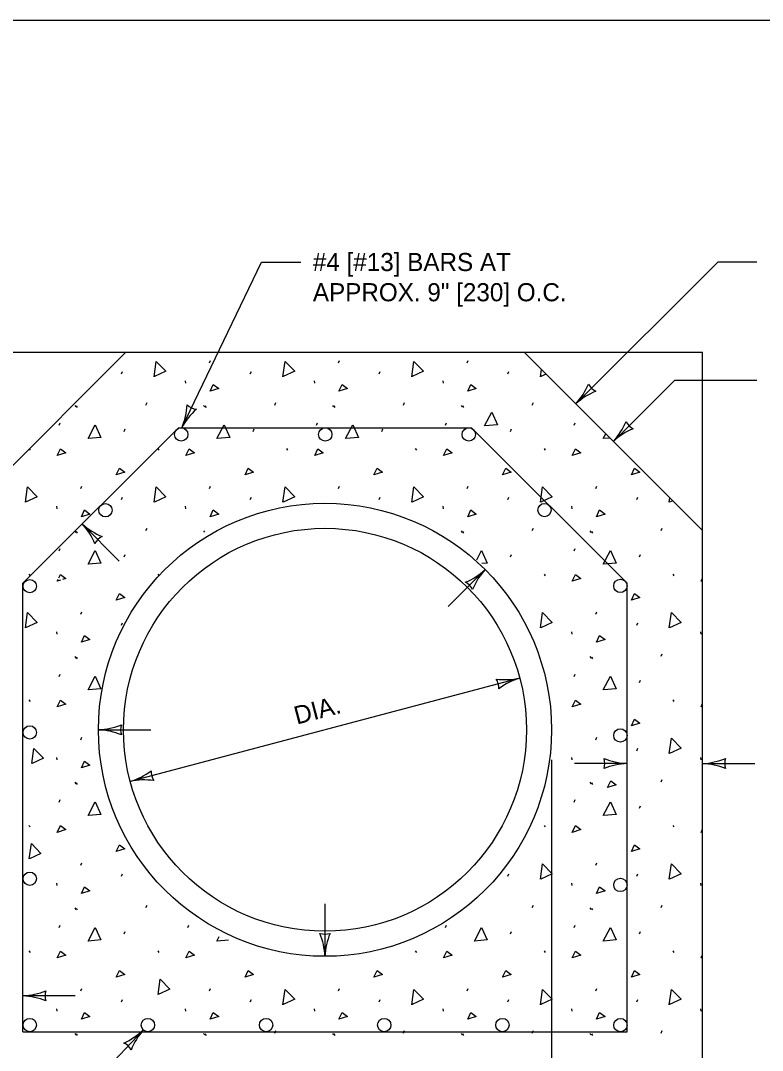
# Model space of a CAD drawing. Extents: x 49991.4 to 50021, y 49987.6 to 50011.4.
# Drawn here: x 50001.927 to 50004.383, y 50007.853 to 50011.263 of the extents above; entities that cross this region are included whole.
import ezdxf

# ---------------------------------------------------------------- set-up
doc = ezdxf.new("R2010")
doc.units = 0
for name, color, linetype in [('Level 1', 7, 'Continuous'), ('Level 2', 7, 'Continuous'), ('Level 3', 7, 'Continuous'), ('Level 4', 7, 'Continuous')]:
    doc.layers.add(name, color=color, linetype=linetype)

msp = doc.modelspace()

# ---------------------------------------------------------------- linework, layer by layer
at = {"layer": 'Level 1'}
for p, q in [((50001.6843, 50009.5741), (50002.275, 50010.1648)), ((50002.275, 50010.1648), (50003.594, 50010.1648)), ((50004.1843, 50009.5745), (50003.594, 50010.1648)), ((50002.5522, 50010.1293), (50002.5557, 50010.1373)), ((50002.9785, 50010.1293), (50002.9821, 50010.1373)), ((50003.4049, 50010.1293), (50003.4085, 50010.1373)), ((50002.2608, 50010.0929), (50002.2643, 50010.1009)), ((50002.6871, 50010.0929), (50002.6907, 50010.1009)), ((50003.1135, 50010.0929), (50003.1171, 50010.1009)), ((50003.5399, 50010.0929), (50003.5434, 50010.1009)), ((50002.4719, 50010.0706), (50002.4728, 50010.0626)), ((50002.8983, 50010.0706), (50002.8992, 50010.0626)), ((50003.3246, 50010.0706), (50003.3255, 50010.0626)), ((50002.1061, 50009.9889), (50002.1097, 50009.9836)), ((50002.1107, 50009.9869), (50002.1142, 50009.9816)), ((50002.3416, 50009.9899), (50002.3451, 50009.9979)), ((50002.5325, 50009.9889), (50002.536, 50009.9836)), ((50002.537, 50009.9869), (50002.5406, 50009.9816)), ((50002.7679, 50009.9899), (50002.7715, 50009.9979)), ((50002.9589, 50009.9889), (50002.9624, 50009.9836)), ((50002.9634, 50009.9869), (50002.967, 50009.9816)), ((50003.1943, 50009.9899), (50003.1979, 50009.9979)), ((50003.3852, 50009.9889), (50003.3888, 50009.9836)), ((50003.3898, 50009.9869), (50003.3934, 50009.9816)), ((50003.6207, 50009.9899), (50003.6242, 50009.9979)), ((50001.9343, 50009.3998), (50002.4493, 50009.9148)), ((50002.0537, 50009.9231), (50002.0573, 50009.9311)), ((50002.2696, 50009.9027), (50002.2732, 50009.9107)), ((50002.4493, 50009.9148), (50003.4196, 50009.9148)), ((50002.696, 50009.9027), (50002.6996, 50009.9107)), ((50002.9065, 50009.9231), (50002.91, 50009.9311)), ((50003.1224, 50009.9027), (50003.1259, 50009.9107)), ((50003.3328, 50009.9231), (50003.3364, 50009.9311)), ((50003.4196, 50009.9148), (50003.9343, 50009.4004)), ((50003.5488, 50009.9027), (50003.5523, 50009.9107)), ((50003.7592, 50009.9231), (50003.7628, 50009.9311)), ((50001.955, 50009.8448), (50001.9578, 50009.8405)), ((50002.3806, 50009.8458), (50002.3842, 50009.8405)), ((50002.807, 50009.8458), (50002.8106, 50009.8405)), ((50003.2334, 50009.8458), (50003.2369, 50009.8405)), ((50003.6598, 50009.8458), (50003.6633, 50009.8405)), ((50002.1258, 50009.7135), (50002.1293, 50009.7215)), ((50002.5522, 50009.7135), (50002.5557, 50009.7215)), ((50002.9785, 50009.7135), (50002.9821, 50009.7215)), ((50003.4049, 50009.7135), (50003.4085, 50009.7215)), ((50003.8313, 50009.7135), (50003.8348, 50009.7215)), ((50002.2608, 50009.6771), (50002.2643, 50009.6851)), ((50002.6871, 50009.6771), (50002.6907, 50009.6851)), ((50003.1135, 50009.6771), (50003.1171, 50009.6851)), ((50003.5399, 50009.6771), (50003.5434, 50009.6851)), ((50003.9663, 50009.6771), (50003.9698, 50009.6851)), ((50002.0455, 50009.6548), (50002.0464, 50009.6468)), ((50002.4719, 50009.6548), (50002.4728, 50009.6468)), ((50003.3246, 50009.6548), (50003.3255, 50009.6468)), ((50003.751, 50009.6548), (50003.7519, 50009.6468)), ((50002.1061, 50009.5731), (50002.1097, 50009.5678)), ((50002.1107, 50009.5711), (50002.1142, 50009.5657)), ((50002.3416, 50009.5741), (50002.3451, 50009.5821)), ((50002.5325, 50009.5731), (50002.5349, 50009.5695)), ((50003.3852, 50009.5731), (50003.3888, 50009.5678)), ((50003.3898, 50009.5711), (50003.3934, 50009.5657)), ((50003.6207, 50009.5741), (50003.6242, 50009.5821)), ((50003.8116, 50009.5731), (50003.8152, 50009.5678)), ((50003.8162, 50009.5711), (50003.8197, 50009.5657)), ((50004.0471, 50009.5741), (50004.0506, 50009.5821)), ((50004.1843, 50007.6648), (50004.1843, 50009.5745)), ((50002.0537, 50009.5073), (50002.0573, 50009.5153)), ((50003.7592, 50009.5073), (50003.7628, 50009.5153)), ((50002.2696, 50009.4869), (50002.2732, 50009.4948)), ((50003.5488, 50009.4869), (50003.5523, 50009.4948)), ((50003.9751, 50009.4869), (50003.9787, 50009.4948)), ((50001.9543, 50009.43), (50001.9578, 50009.4247)), ((50002.3806, 50009.43), (50002.3842, 50009.4247)), ((50003.6598, 50009.43), (50003.6633, 50009.4247)), ((50004.0861, 50009.43), (50004.0897, 50009.4247)), ((50001.9343, 50007.9148), (50001.9343, 50009.3998)), ((50003.9343, 50007.9148), (50003.9343, 50009.4004)), ((50002.1258, 50009.2977), (50002.1293, 50009.3057)), ((50003.8313, 50009.2977), (50003.8348, 50009.3057)), ((50002.2608, 50009.2613), (50002.2643, 50009.2693)), ((50003.9663, 50009.2613), (50003.9698, 50009.2693)), ((50002.0455, 50009.239), (50002.0464, 50009.231)), ((50003.751, 50009.239), (50003.7519, 50009.231)), ((50004.1774, 50009.239), (50004.1783, 50009.231)), ((50002.1061, 50009.1573), (50002.1097, 50009.152)), ((50002.1107, 50009.1553), (50002.1142, 50009.1499)), ((50003.8116, 50009.1573), (50003.8152, 50009.152)), ((50003.8162, 50009.1553), (50003.8197, 50009.1499)), ((50004.0471, 50009.1583), (50004.0506, 50009.1663)), ((50002.0537, 50009.0915), (50002.0573, 50009.0995)), ((50003.7592, 50009.0915), (50003.7628, 50009.0995)), ((50003.9751, 50009.071), (50003.9787, 50009.079)), ((50001.9543, 50009.0142), (50001.9578, 50009.0089)), ((50004.0861, 50009.0142), (50004.0897, 50009.0089)), ((50002.1258, 50008.8819), (50002.1293, 50008.8899)), ((50003.8313, 50008.8819), (50003.8348, 50008.8899)), ((50003.9663, 50008.8455), (50003.9698, 50008.8535)), ((50002.0455, 50008.8232), (50002.0464, 50008.8152)), ((50003.751, 50008.8232), (50003.7519, 50008.8152)), ((50004.1774, 50008.8232), (50004.1783, 50008.8152)), ((50004.0471, 50008.7425), (50004.0506, 50008.7505)), ((50002.1061, 50008.7415), (50002.1097, 50008.7361)), ((50002.1107, 50008.7394), (50002.1142, 50008.7341)), ((50003.8116, 50008.7415), (50003.8152, 50008.7361)), ((50003.8162, 50008.7394), (50003.8197, 50008.7341)), ((50002.0537, 50008.6756), (50002.0573, 50008.6836)), ((50003.7592, 50008.6756), (50003.7628, 50008.6836)), ((50003.9751, 50008.6552), (50003.9787, 50008.6632)), ((50001.9543, 50008.5984), (50001.9578, 50008.5931)), ((50003.6598, 50008.5984), (50003.6633, 50008.5931)), ((50004.0861, 50008.5984), (50004.0897, 50008.5931)), ((50002.1258, 50008.4661), (50002.1293, 50008.4741)), ((50003.8313, 50008.4661), (50003.8348, 50008.4741)), ((50002.0455, 50008.4074), (50002.0464, 50008.3994)), ((50002.2608, 50008.4297), (50002.2643, 50008.4377)), ((50003.5399, 50008.4297), (50003.5434, 50008.4377)), ((50003.751, 50008.4074), (50003.7519, 50008.3994)), ((50003.9663, 50008.4297), (50003.9698, 50008.4377)), ((50004.1774, 50008.4074), (50004.1783, 50008.3994)), ((50002.1061, 50008.3257), (50002.1097, 50008.3203)), ((50002.1107, 50008.3236), (50002.1142, 50008.3183)), ((50002.3416, 50008.3267), (50002.3451, 50008.3346)), ((50003.6207, 50008.3267), (50003.6242, 50008.3346)), ((50003.8116, 50008.3257), (50003.8152, 50008.3203)), ((50003.8162, 50008.3236), (50003.8197, 50008.3183)), ((50004.0471, 50008.3267), (50004.0506, 50008.3346)), ((50002.0537, 50008.2598), (50002.0573, 50008.2678)), ((50002.4801, 50008.2598), (50002.4836, 50008.2678)), ((50003.3328, 50008.2598), (50003.3364, 50008.2678)), ((50003.7592, 50008.2598), (50003.7628, 50008.2678)), ((50002.2696, 50008.2394), (50002.2732, 50008.2474)), ((50003.5488, 50008.2394), (50003.5523, 50008.2474)), ((50003.9751, 50008.2394), (50003.9787, 50008.2474)), ((50001.9543, 50008.1826), (50001.9578, 50008.1772)), ((50002.3806, 50008.1826), (50002.3842, 50008.1772)), ((50003.2334, 50008.1826), (50003.2369, 50008.1772)), ((50003.6598, 50008.1826), (50003.6633, 50008.1772)), ((50004.0861, 50008.1826), (50004.0897, 50008.1772)), ((50002.1258, 50008.0503), (50002.1293, 50008.0583)), ((50002.5522, 50008.0503), (50002.5557, 50008.0583)), ((50002.9785, 50008.0503), (50002.9821, 50008.0583)), ((50003.4049, 50008.0503), (50003.4085, 50008.0583)), ((50003.8313, 50008.0503), (50003.8348, 50008.0583)), ((50002.2608, 50008.0138), (50002.2643, 50008.0218)), ((50002.6871, 50008.0138), (50002.6907, 50008.0218)), ((50003.1135, 50008.0138), (50003.1171, 50008.0218)), ((50003.5399, 50008.0138), (50003.5434, 50008.0218)), ((50003.9663, 50008.0138), (50003.9698, 50008.0218)), ((50002.0455, 50007.9915), (50002.0464, 50007.9836)), ((50002.4719, 50007.9915), (50002.4728, 50007.9836)), ((50002.8983, 50007.9915), (50002.8992, 50007.9836)), ((50003.3246, 50007.9915), (50003.3255, 50007.9836)), ((50003.751, 50007.9915), (50003.7519, 50007.9836)), ((50004.1774, 50007.9915), (50004.1783, 50007.9836)), ((50001.9343, 50007.9148), (50003.9343, 50007.9148)), ((50002.1061, 50007.9098), (50002.1097, 50007.9045)), ((50002.1107, 50007.9078), (50002.1142, 50007.9025)), ((50002.5325, 50007.9098), (50002.536, 50007.9045)), ((50002.537, 50007.9078), (50002.5406, 50007.9025)), ((50002.7679, 50007.9108), (50002.7715, 50007.9188)), ((50002.9589, 50007.9098), (50002.9624, 50007.9045)), ((50002.9634, 50007.9078), (50002.967, 50007.9025)), ((50003.1943, 50007.9108), (50003.1979, 50007.9188)), ((50003.3852, 50007.9098), (50003.3888, 50007.9045)), ((50003.3898, 50007.9078), (50003.3934, 50007.9025)), ((50003.6207, 50007.9108), (50003.6242, 50007.9188)), ((50003.8116, 50007.9098), (50003.8152, 50007.9045)), ((50003.8162, 50007.9078), (50003.8197, 50007.9025)), ((50004.0471, 50007.9108), (50004.0506, 50007.9188))]:
    msp.add_line(p, q, dxfattribs=at)
msp.add_lwpolyline([(50008.6146, 50011.2628), (50000.3356, 50011.2628), (50000.3356, 50000.0624), (50008.6146, 50000.0624)], close=True, dxfattribs=at)
for points in [[(50002.3688, 50010.0837), (50002.3758, 50010.1345), (50002.4076, 50010.1017), (50002.3696, 50010.084)], [(50002.7952, 50010.0837), (50002.8022, 50010.1345), (50002.834, 50010.1017), (50002.796, 50010.084)], [(50003.2215, 50010.0837), (50003.2286, 50010.1345), (50003.2604, 50010.1017), (50003.2224, 50010.084)], [(50003.6479, 50010.0837), (50003.6512, 50010.1072)], [(50003.6662, 50010.0921), (50003.6488, 50010.084)], [(50002.1555, 50010.0453), (50002.156, 50010.045), (50002.1548, 50010.0446)], [(50002.5539, 50010.0361), (50002.5646, 50010.0583), (50002.5823, 50010.045), (50002.5539, 50010.0361)], [(50002.9803, 50010.0361), (50002.991, 50010.0583), (50003.0087, 50010.045), (50002.9803, 50010.0361)], [(50003.4067, 50010.0361), (50003.4173, 50010.0583), (50003.4351, 50010.045), (50003.4067, 50010.0361)], [(50003.4626, 50009.9207), (50003.4866, 50009.966), (50003.5052, 50009.9242), (50003.4635, 50009.9207)], [(50002.1498, 50009.8787), (50002.1737, 50009.924), (50002.1924, 50009.8822), (50002.1506, 50009.8787)], [(50002.5761, 50009.8787), (50002.6001, 50009.924), (50002.6188, 50009.8822), (50002.577, 50009.8787)], [(50003.0025, 50009.8787), (50003.0265, 50009.924), (50003.0451, 50009.8822), (50003.0034, 50009.8787)], [(50003.8553, 50009.8787), (50003.8638, 50009.8948)], [(50003.878, 50009.8805), (50003.8561, 50009.8787)], [(50002.0475, 50009.8227), (50002.0582, 50009.8449), (50002.0759, 50009.8316), (50002.0475, 50009.8227)], [(50002.4739, 50009.8227), (50002.4845, 50009.8449), (50002.5023, 50009.8316), (50002.4739, 50009.8227)], [(50002.9003, 50009.8227), (50002.9109, 50009.8449), (50002.9287, 50009.8316), (50002.9003, 50009.8227)], [(50003.3266, 50009.8227), (50003.3373, 50009.8449), (50003.355, 50009.8316), (50003.3266, 50009.8227)], [(50003.753, 50009.8227), (50003.7637, 50009.8449), (50003.7814, 50009.8316), (50003.753, 50009.8227)], [(50002.2432, 50009.7593), (50002.2538, 50009.7815), (50002.2716, 50009.7681), (50002.2432, 50009.7593)], [(50002.6695, 50009.7593), (50002.6802, 50009.7815), (50002.698, 50009.7681), (50002.6695, 50009.7593)], [(50003.0959, 50009.7593), (50003.1066, 50009.7815), (50003.1243, 50009.7681), (50003.0959, 50009.7593)], [(50003.5223, 50009.7593), (50003.533, 50009.7815), (50003.5507, 50009.7681), (50003.5223, 50009.7593)], [(50003.9487, 50009.7593), (50003.9593, 50009.7815), (50003.9771, 50009.7681), (50003.9487, 50009.7593)], [(50001.9424, 50009.6679), (50001.9495, 50009.7187), (50001.9813, 50009.6858), (50001.9432, 50009.6682)], [(50002.3688, 50009.6679), (50002.3758, 50009.7187), (50002.4076, 50009.6858), (50002.3696, 50009.6682)], [(50002.7952, 50009.6679), (50002.8022, 50009.7187), (50002.834, 50009.6858), (50002.796, 50009.6682)], [(50003.2215, 50009.6679), (50003.2286, 50009.7187), (50003.2604, 50009.6858), (50003.2224, 50009.6682)], [(50003.6479, 50009.6679), (50003.655, 50009.7187), (50003.6868, 50009.6858), (50003.6488, 50009.6682)], [(50004.0743, 50009.6679), (50004.0763, 50009.6824)], [(50004.0856, 50009.6731), (50004.0751, 50009.6682)], [(50002.1276, 50009.6203), (50002.1382, 50009.6425), (50002.156, 50009.6292), (50002.1276, 50009.6203)], [(50002.5539, 50009.6203), (50002.5646, 50009.6425), (50002.5823, 50009.6292), (50002.5539, 50009.6203)], [(50003.4067, 50009.6203), (50003.4173, 50009.6425), (50003.4351, 50009.6292), (50003.4067, 50009.6203)], [(50003.8331, 50009.6203), (50003.8437, 50009.6425), (50003.8615, 50009.6292), (50003.8331, 50009.6203)], [(50002.1498, 50009.4629), (50002.1737, 50009.5082), (50002.1924, 50009.4664), (50002.1506, 50009.4629)], [(50003.4368, 50009.4778), (50003.4529, 50009.5082), (50003.4715, 50009.4664), (50003.4539, 50009.4649)], [(50003.8553, 50009.4629), (50003.8792, 50009.5082), (50003.8979, 50009.4664), (50003.8561, 50009.4629)], [(50002.0527, 50009.4178), (50002.0582, 50009.4291), (50002.0759, 50009.4158), (50002.0653, 50009.4125)], [(50003.753, 50009.4069), (50003.7637, 50009.4291), (50003.7814, 50009.4158), (50003.753, 50009.4069)], [(50002.0475, 50009.4069), (50002.0507, 50009.4136)], [(50002.0583, 50009.4103), (50002.0475, 50009.4069)], [(50004.1794, 50009.4069), (50004.1843, 50009.4172)], [(50004.1843, 50009.4084), (50004.1794, 50009.4069)], [(50002.2432, 50009.3435), (50002.2538, 50009.3657), (50002.2716, 50009.3523), (50002.2432, 50009.3435)], [(50003.9487, 50009.3435), (50003.9593, 50009.3657), (50003.9771, 50009.3523), (50003.9487, 50009.3435)], [(50001.9424, 50009.2521), (50001.9495, 50009.3029), (50001.9813, 50009.27), (50001.9432, 50009.2524)], [(50003.6479, 50009.2521), (50003.655, 50009.3029), (50003.6868, 50009.27), (50003.6488, 50009.2524)], [(50004.0743, 50009.2521), (50004.0813, 50009.3029), (50004.1131, 50009.27), (50004.0751, 50009.2524)], [(50002.1276, 50009.2045), (50002.1382, 50009.2267), (50002.156, 50009.2133), (50002.1276, 50009.2045)], [(50003.8331, 50009.2045), (50003.8437, 50009.2267), (50003.8615, 50009.2133), (50003.8331, 50009.2045)], [(50002.1498, 50009.0471), (50002.1737, 50009.0923), (50002.1924, 50009.0506), (50002.1506, 50009.0471)], [(50003.8553, 50009.0471), (50003.8792, 50009.0923), (50003.8979, 50009.0506), (50003.8561, 50009.0471)], [(50002.0475, 50008.9911), (50002.0582, 50009.0133), (50002.0759, 50009), (50002.0475, 50008.9911)], [(50003.753, 50008.9911), (50003.7637, 50009.0133), (50003.7814, 50009), (50003.753, 50008.9911)], [(50004.1794, 50008.9911), (50004.1843, 50009.0014)], [(50004.1843, 50008.9926), (50004.1794, 50008.9911)], [(50003.9487, 50008.9276), (50003.9593, 50008.9498), (50003.9771, 50008.9365), (50003.9487, 50008.9276)], [(50004.0743, 50008.8363), (50004.0813, 50008.887), (50004.1131, 50008.8542), (50004.0751, 50008.8366)], [(50001.9635, 50008.8027), (50001.9706, 50008.8534), (50002.0024, 50008.8206), (50001.9643, 50008.803)], [(50002.1276, 50008.7886), (50002.1382, 50008.8108), (50002.156, 50008.7975), (50002.1276, 50008.7886)], [(50003.8696, 50008.7232), (50003.8802, 50008.7454), (50003.898, 50008.7321), (50003.8696, 50008.7232)], [(50002.1498, 50008.6312), (50002.1737, 50008.6765), (50002.1924, 50008.6348), (50002.1506, 50008.6312)], [(50003.8553, 50008.6312), (50003.8792, 50008.6765), (50003.8979, 50008.6348), (50003.8561, 50008.6312)], [(50002.0475, 50008.5753), (50002.0582, 50008.5975), (50002.0759, 50008.5842), (50002.0475, 50008.5753)], [(50003.753, 50008.5753), (50003.7637, 50008.5975), (50003.7814, 50008.5842), (50003.753, 50008.5753)], [(50004.1794, 50008.5753), (50004.1843, 50008.5856)], [(50004.1843, 50008.5768), (50004.1794, 50008.5753)], [(50001.9551, 50008.4878), (50001.9622, 50008.5385), (50001.994, 50008.5057), (50001.9559, 50008.4881)], [(50002.2432, 50008.5118), (50002.2538, 50008.534), (50002.2716, 50008.5207), (50002.2432, 50008.5118)], [(50003.9487, 50008.5118), (50003.9593, 50008.534), (50003.9771, 50008.5207), (50003.9487, 50008.5118)], [(50003.6479, 50008.4205), (50003.655, 50008.4712), (50003.6868, 50008.4384), (50003.6488, 50008.4208)], [(50004.0743, 50008.4205), (50004.0813, 50008.4712), (50004.1131, 50008.4384), (50004.0751, 50008.4208)], [(50002.1276, 50008.3728), (50002.1382, 50008.395), (50002.156, 50008.3817), (50002.1276, 50008.3728)], [(50003.8331, 50008.3728), (50003.8437, 50008.395), (50003.8615, 50008.3817), (50003.8331, 50008.3728)], [(50002.1498, 50008.2154), (50002.1737, 50008.2607), (50002.1924, 50008.219), (50002.1506, 50008.2154)], [(50003.4289, 50008.2154), (50003.4529, 50008.2607), (50003.4715, 50008.219), (50003.4298, 50008.2154)], [(50003.8553, 50008.2154), (50003.8792, 50008.2607), (50003.8979, 50008.219), (50003.8561, 50008.2154)], [(50002.5761, 50008.2154), (50002.5843, 50008.2309)], [(50002.6144, 50008.2186), (50002.577, 50008.2154)], [(50002.0475, 50008.1595), (50002.0582, 50008.1817), (50002.0759, 50008.1684), (50002.0475, 50008.1595)], [(50002.4739, 50008.1595), (50002.4845, 50008.1817), (50002.5023, 50008.1684), (50002.4739, 50008.1595)], [(50003.3266, 50008.1595), (50003.3373, 50008.1817), (50003.355, 50008.1684), (50003.3266, 50008.1595)], [(50003.753, 50008.1595), (50003.7637, 50008.1817), (50003.7814, 50008.1684), (50003.753, 50008.1595)], [(50004.1794, 50008.1595), (50004.1843, 50008.1698)], [(50004.1843, 50008.161), (50004.1794, 50008.1595)], [(50002.2432, 50008.096), (50002.2538, 50008.1182), (50002.2716, 50008.1049), (50002.2432, 50008.096)], [(50002.6695, 50008.096), (50002.6802, 50008.1182), (50002.698, 50008.1049), (50002.6695, 50008.096)], [(50003.0959, 50008.096), (50003.1066, 50008.1182), (50003.1243, 50008.1049), (50003.0959, 50008.096)], [(50003.5223, 50008.096), (50003.533, 50008.1182), (50003.5507, 50008.1049), (50003.5223, 50008.096)], [(50003.9487, 50008.096), (50003.9593, 50008.1182), (50003.9771, 50008.1049), (50003.9487, 50008.096)], [(50002.3815, 50008.0383), (50002.3885, 50008.089), (50002.4203, 50008.0562), (50002.3823, 50008.0386)], [(50002.7952, 50008.0047), (50002.8022, 50008.0554), (50002.834, 50008.0226), (50002.796, 50008.005)], [(50003.2215, 50008.0047), (50003.2286, 50008.0554), (50003.2604, 50008.0226), (50003.2224, 50008.005)], [(50003.6479, 50008.0047), (50003.655, 50008.0554), (50003.6868, 50008.0226), (50003.6488, 50008.005)], [(50004.0743, 50008.0047), (50004.0813, 50008.0554), (50004.1131, 50008.0226), (50004.0751, 50008.005)], [(50002.1276, 50007.957), (50002.1382, 50007.9792), (50002.156, 50007.9659), (50002.1276, 50007.957)], [(50002.5539, 50007.957), (50002.5646, 50007.9792), (50002.5823, 50007.9659), (50002.5539, 50007.957)], [(50002.9803, 50007.957), (50002.991, 50007.9792), (50003.0087, 50007.9659), (50002.9803, 50007.957)], [(50003.4067, 50007.957), (50003.4173, 50007.9792), (50003.4351, 50007.9659), (50003.4067, 50007.957)], [(50003.8331, 50007.957), (50003.8437, 50007.9792), (50003.8615, 50007.9659), (50003.8331, 50007.957)]]:
    msp.add_lwpolyline(points, dxfattribs=at)
for centre, radius in [((50002.4584, 50009.8927), 0.0221), ((50002.9353, 50009.8927), 0.0221), ((50003.4104, 50009.8927), 0.0221), ((50002.9343, 50008.9148), 0.75), ((50002.2074, 50009.6417), 0.0221), ((50003.6611, 50009.6423), 0.0221), ((50002.9343, 50008.9148), 0.667), ((50001.9569, 50009.3903), 0.0221), ((50003.9122, 50009.3912), 0.0221), ((50001.9569, 50008.906), 0.0221), ((50003.9122, 50008.8961), 0.0221), ((50001.9569, 50008.4217), 0.0221), ((50003.9122, 50008.401), 0.0221), ((50001.9569, 50007.9374), 0.0221), ((50002.3481, 50007.9374), 0.0221), ((50002.7393, 50007.9374), 0.0221), ((50003.1305, 50007.9374), 0.0221), ((50003.5217, 50007.9374), 0.0221), ((50003.9125, 50007.9372), 0.0221)]:
    msp.add_circle(centre, radius, dxfattribs=at)
at = {"layer": 'Level 3'}
for p, q in [((50002.4602, 50009.9148), (50002.7244, 50010.4635)), ((50002.7244, 50010.4635), (50002.8542, 50010.4635)), ((50004.2345, 50010.4635), (50003.7649, 50009.9939)), ((50004.3643, 50010.4635), (50004.2345, 50010.4635)), ((50004.0922, 50010.0727), (50003.8892, 50009.8697)), ((50004.0922, 50010.0727), (50004.3643, 50010.0727)), ((50002.2534, 50009.4736), (50002.1308, 50009.5963)), ((50003.4646, 50009.4451), (50003.342, 50009.3225)), ((50003.5789, 50009.0861), (50002.2896, 50008.7436)), ((50002.1843, 50008.9148), (50002.3577, 50008.9148)), ((50003.6843, 50008.8148), (50003.6841, 50007.3555)), ((50003.9343, 50008.8032), (50003.7609, 50008.8032)), ((50004.1843, 50008.803), (50004.3577, 50008.803)), ((50002.9343, 50008.3382), (50002.9343, 50008.1648)), ((50002.1077, 50008.0339), (50001.9343, 50008.0339)), ((50002.3329, 50007.9214), (50001.8998, 50007.4655))]:
    msp.add_line(p, q, dxfattribs=at)
for centre, radius, start, end in [((50003.5922, 50010.1503), 0.233, 317.8273, 337.0772), ((50003.8556, 50010.0846), 0.0548, 207.1388, 242.8612), ((50003.9155, 50009.8304), 0.2223, 112.456, 132.6395), ((50002.2455, 50010.0054), 0.233, 337.117, 356.3668), ((50002.6564, 50009.8102), 0.2223, 131.7457, 151.9292), ((50002.5158, 50010.0303), 0.0548, 226.4285, 262.1508), ((50004.0397, 50009.7061), 0.2223, 112.456, 132.6395), ((50003.7165, 50010.0261), 0.233, 317.8273, 337.0772), ((50003.9798, 50009.9603), 0.0548, 207.1388, 242.8612), ((50001.9672, 50009.4458), 0.2223, 22.4335, 42.617), ((50002.2873, 50009.7689), 0.233, 227.8048, 247.0546), ((50002.2214, 50009.5056), 0.0548, 117.1163, 152.8387), ((50003.314, 50009.6087), 0.2223, 292.456, 312.6395), ((50003.6373, 50009.2887), 0.233, 137.8273, 157.0772), ((50003.374, 50009.3545), 0.0548, 27.1388, 62.8612), ((50003.5307, 50009.3031), 0.2223, 262.3331, 282.5166), ((50003.6498, 50008.8641), 0.233, 107.7044, 126.9542), ((50003.455, 50009.0532), 0.0548, 357.0159, 32.7382), ((50002.1728, 50009.1475), 0.233, 272.8273, 292.0772), ((50002.3125, 50008.9148), 0.0548, 162.1388, 197.8612), ((50002.1751, 50008.6927), 0.2223, 67.456, 87.6395), ((50003.9435, 50009.0253), 0.2223, 247.456, 267.6395), ((50003.8061, 50008.8032), 0.0548, 342.1388, 17.8612), ((50004.1728, 50009.0357), 0.233, 272.8273, 292.0772), ((50004.3125, 50008.803), 0.0548, 162.1388, 197.8612), ((50002.2188, 50008.9655), 0.233, 287.7044, 306.9542), ((50002.4136, 50008.7765), 0.0548, 177.0159, 212.7382), ((50003.9458, 50008.5705), 0.233, 92.8273, 112.0772), ((50004.1751, 50008.5809), 0.2223, 67.456, 87.6395), ((50002.3378, 50008.5265), 0.2223, 82.3331, 102.5166), ((50002.9343, 50008.293), 0.0548, 252.1388, 287.8612), ((50002.7016, 50008.1533), 0.233, 2.8273, 22.0772), ((50003.1564, 50008.1556), 0.2223, 157.456, 177.6395), ((50001.9228, 50008.2666), 0.233, 272.8273, 292.0772), ((50001.9251, 50007.8118), 0.2223, 67.456, 87.6395), ((50002.0625, 50008.0339), 0.0548, 162.1388, 197.8612), ((50002.1781, 50008.081), 0.2223, 293.9248, 314.1083), ((50002.5095, 50007.7694), 0.233, 139.2961, 158.546), ((50002.2446, 50007.8284), 0.0548, 28.6076, 64.33)]:
    msp.add_arc(centre, radius, start, end, dxfattribs=at)
at = {"layer": 'Level 4'}
for p, q in [((50001.6843, 50010.1648), (50002.275, 50010.1648)), ((50003.594, 50010.1648), (50004.1843, 50010.1648)), ((50004.1843, 50009.5745), (50004.1843, 50010.1648))]:
    msp.add_line(p, q, dxfattribs=at)

# ---------------------------------------------------------------- texts
at = {"layer": 'Level 2'}
for s, p in [('#4 [#13] BARS AT', (50002.8942, 50010.4335)), ('APPROX. 9" [230] O.C.', (50002.8942, 50010.3335))]:
    msp.add_text(s, height=0.06, dxfattribs=at).set_placement(p)
msp.add_text('DIA.', height=0.06, rotation=14.736, dxfattribs=at).set_placement((50002.841, 50008.9317))

doc.saveas('drawing.dxf')
